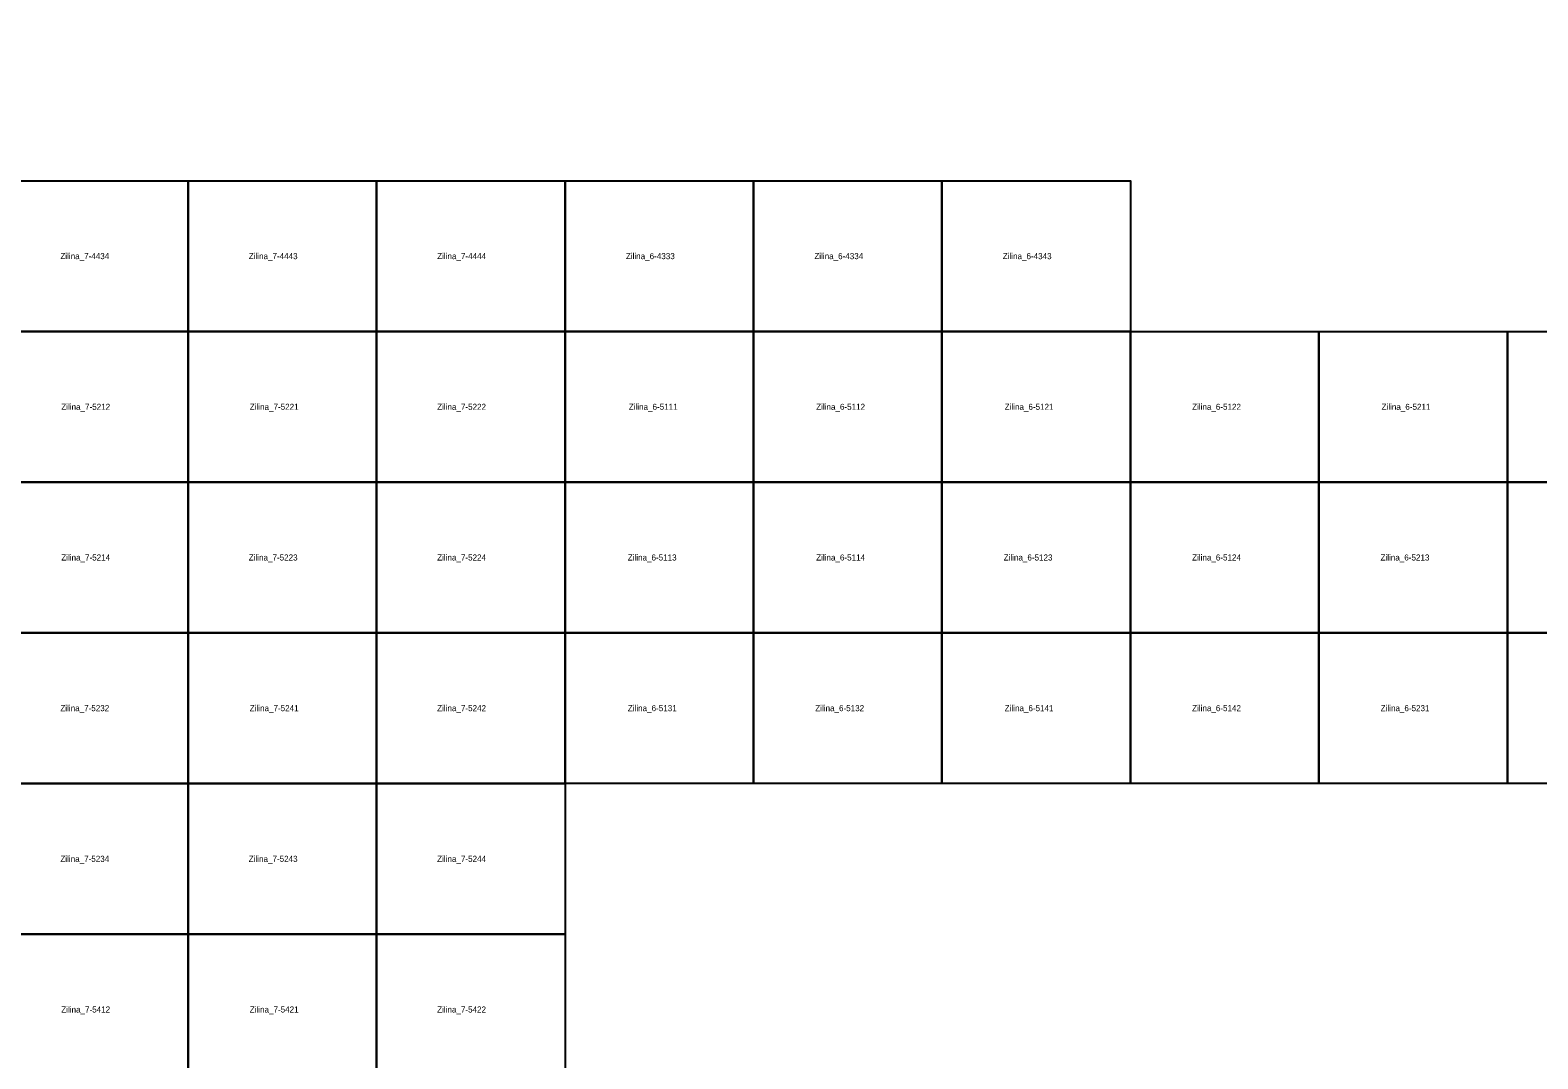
# Model space of a CAD drawing. Extents: x -445938 to -437812, y -1177250 to -1169500.
# Drawn here: x -443387 to -440887, y -1171207 to -1169500 of the extents above; entities that cross this region are included whole.
import ezdxf

# ---------------------------------------------------------------- set-up
doc = ezdxf.new("R2010")
doc.units = 0
for name, color, linetype in [('Vrstva 1', 7, 'Continuous'), ('Vrstva 4', 7, 'Continuous'), ('Vrstva 6', 7, 'Continuous')]:
    doc.layers.add(name, color=color, linetype=linetype)

msp = doc.modelspace()

# ---------------------------------------------------------------- linework, layer by layer
at = {"layer": 'Vrstva 1'}
for points in [[(-440625, -1175500), (-441562.5, -1175500), (-441562.5, -1175000), (-442812.5, -1175000), (-442812.5, -1175750), (-443437.5, -1175750), (-443437.5, -1177250), (-445000, -1177250), (-445000, -1175500), (-445312.5, -1175500), (-445312.5, -1173750), (-445937.5, -1173750), (-445937.5, -1172250), (-445625, -1172250), (-445625, -1169500), (-444062.5, -1169500), (-444062.5, -1169750), (-441562.5, -1169750), (-441562.5, -1170000), (-440000, -1170000)], [(-440000, -1170750), (-442500, -1170750), (-442500, -1171250), (-441562.5, -1171250), (-441562.5, -1171500), (-440937.5, -1171500), (-440937.5, -1172000), (-440625, -1172000)]]:
    msp.add_lwpolyline(points, dxfattribs=at)
at = {"layer": 'Vrstva 4'}
for points in [[(-443125, -1169750), (-443125, -1170000), (-443437.5, -1170000), (-443437.5, -1169750)], [(-442812.5, -1169750), (-442812.5, -1170000), (-443125, -1170000), (-443125, -1169750)], [(-442500, -1169750), (-442500, -1170000), (-442812.5, -1170000), (-442812.5, -1169750)], [(-442187.5, -1169750), (-442187.5, -1170000), (-442500, -1170000), (-442500, -1169750)], [(-441875, -1169750), (-441875, -1170000), (-442187.5, -1170000), (-442187.5, -1169750)], [(-441562.5, -1169750), (-441562.5, -1170000), (-441875, -1170000), (-441875, -1169750)], [(-443125, -1170000), (-443125, -1170250), (-443437.5, -1170250), (-443437.5, -1170000)], [(-442812.5, -1170000), (-442812.5, -1170250), (-443125, -1170250), (-443125, -1170000)], [(-442500, -1170000), (-442500, -1170250), (-442812.5, -1170250), (-442812.5, -1170000)], [(-442187.5, -1170000), (-442187.5, -1170250), (-442500, -1170250), (-442500, -1170000)], [(-441875, -1170000), (-441875, -1170250), (-442187.5, -1170250), (-442187.5, -1170000)], [(-441562.5, -1170000), (-441562.5, -1170250), (-441875, -1170250), (-441875, -1170000)], [(-441250, -1170000), (-441250, -1170250), (-441562.5, -1170250), (-441562.5, -1170000)], [(-440937.5, -1170000), (-440937.5, -1170250), (-441250, -1170250), (-441250, -1170000)], [(-440625, -1170000), (-440625, -1170250), (-440937.5, -1170250), (-440937.5, -1170000)], [(-443125, -1170250), (-443125, -1170500), (-443437.5, -1170500), (-443437.5, -1170250)], [(-442812.5, -1170250), (-442812.5, -1170500), (-443125, -1170500), (-443125, -1170250)], [(-442500, -1170250), (-442500, -1170500), (-442812.5, -1170500), (-442812.5, -1170250)], [(-442187.5, -1170250), (-442187.5, -1170500), (-442500, -1170500), (-442500, -1170250)], [(-441875, -1170250), (-441875, -1170500), (-442187.5, -1170500), (-442187.5, -1170250)], [(-441562.5, -1170250), (-441562.5, -1170500), (-441875, -1170500), (-441875, -1170250)], [(-441250, -1170250), (-441250, -1170500), (-441562.5, -1170500), (-441562.5, -1170250)], [(-440937.5, -1170250), (-440937.5, -1170500), (-441250, -1170500), (-441250, -1170250)], [(-440625, -1170250), (-440625, -1170500), (-440937.5, -1170500), (-440937.5, -1170250)], [(-443125, -1170500), (-443125, -1170750), (-443437.5, -1170750), (-443437.5, -1170500)], [(-442812.5, -1170500), (-442812.5, -1170750), (-443125, -1170750), (-443125, -1170500)], [(-442500, -1170500), (-442500, -1170750), (-442812.5, -1170750), (-442812.5, -1170500)], [(-442187.5, -1170500), (-442187.5, -1170750), (-442500, -1170750), (-442500, -1170500)], [(-441875, -1170500), (-441875, -1170750), (-442187.5, -1170750), (-442187.5, -1170500)], [(-441562.5, -1170500), (-441562.5, -1170750), (-441875, -1170750), (-441875, -1170500)], [(-441250, -1170500), (-441250, -1170750), (-441562.5, -1170750), (-441562.5, -1170500)], [(-440937.5, -1170500), (-440937.5, -1170750), (-441250, -1170750), (-441250, -1170500)], [(-440625, -1170500), (-440625, -1170750), (-440937.5, -1170750), (-440937.5, -1170500)], [(-443125, -1170750), (-443125, -1171000), (-443437.5, -1171000), (-443437.5, -1170750)], [(-442812.5, -1170750), (-442812.5, -1171000), (-443125, -1171000), (-443125, -1170750)], [(-442500, -1170750), (-442500, -1171000), (-442812.5, -1171000), (-442812.5, -1170750)], [(-443125, -1171000), (-443125, -1171250), (-443437.5, -1171250), (-443437.5, -1171000)], [(-442812.5, -1171000), (-442812.5, -1171250), (-443125, -1171250), (-443125, -1171000)], [(-442500, -1171000), (-442500, -1171250), (-442812.5, -1171250), (-442812.5, -1171000)]]:
    msp.add_lwpolyline(points, close=True, dxfattribs=at)

# ---------------------------------------------------------------- texts
at = {"layer": 'Vrstva 6'}
for s, p in [('Zilina_7-4434', (-443336.914, -1169880)), ('Zilina_7-4443', (-443024.572, -1169880)), ('Zilina_7-4444', (-442712.072, -1169880)), ('Zilina_6-4333', (-442399.138, -1169880)), ('Zilina_6-4334', (-442086.638, -1169880)), ('Zilina_6-4343', (-441774.296, -1169880)), ('Zilina_7-5212', (-443335.379, -1170130)), ('Zilina_7-5221', (-443022.878, -1170130)), ('Zilina_7-5222', (-442712.072, -1170130)), ('Zilina_6-5111', (-442394.376, -1170130)), ('Zilina_6-5112', (-442083.568, -1170130)), ('Zilina_6-5121', (-441771.068, -1170130)), ('Zilina_6-5122', (-441460.261, -1170130)), ('Zilina_6-5211', (-441146.068, -1170130)), ('Zilina_7-5214', (-443335.379, -1170380)), ('Zilina_7-5223', (-443024.572, -1170380)), ('Zilina_7-5224', (-442712.072, -1170380)), ('Zilina_6-5113', (-442396.068, -1170380)), ('Zilina_6-5114', (-442083.568, -1170380)), ('Zilina_6-5123', (-441772.761, -1170380)), ('Zilina_6-5124', (-441460.261, -1170380)), ('Zilina_6-5213', (-441147.761, -1170380)), ('Zilina_7-5232', (-443336.914, -1170630)), ('Zilina_7-5241', (-443022.878, -1170630)), ('Zilina_7-5242', (-442712.072, -1170630)), ('Zilina_6-5131', (-442395.91, -1170630)), ('Zilina_6-5132', (-442085.104, -1170630)), ('Zilina_6-5141', (-441771.068, -1170630)), ('Zilina_6-5142', (-441460.261, -1170630)), ('Zilina_6-5231', (-441147.603, -1170630)), ('Zilina_7-5234', (-443336.914, -1170880)), ('Zilina_7-5243', (-443024.572, -1170880)), ('Zilina_7-5244', (-442712.072, -1170880)), ('Zilina_7-5412', (-443335.379, -1171130)), ('Zilina_7-5421', (-443022.878, -1171130)), ('Zilina_7-5422', (-442712.072, -1171130))]:
    msp.add_text(s, height=10, dxfattribs=at).set_placement(p)

doc.saveas('drawing.dxf')
